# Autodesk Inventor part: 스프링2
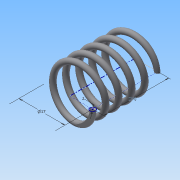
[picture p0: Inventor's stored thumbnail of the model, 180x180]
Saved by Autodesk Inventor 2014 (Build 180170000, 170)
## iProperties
Created: 2016-01
Part Number: 스프링2
Material: 강철, 탄소
Document SubType Name: Modeling
Designer: Administrator
Density: 7.87 g/cm^3
Appearance: 반연마
Mass: 6.44239 g
Surface Area: 16.6857 cm^2
Volume: 0.818602 cm^3
Author: Administrator
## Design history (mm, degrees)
sketch "스케치1"
  geometry: L1 (0, 0)-(8.5, 0); L2 (8.5, 0)-(8.5, 17.5); L3 (8.5, 17.5)-(0, 17.5); L4 (0, 17.5)-(0, 0); C1 r 1 at (8.5, 0)
  constraints: 8 end point, 2 parallel, 1 centre point, 1 coincident, 1 horizontal, 1 perpendicular
  dimensions: "d0" = 17 diameter of L2 L4; "d1" = 17.5 distance of L1.end L2.end (derived); "d2" = 2 diameter of C1
feature "코일1" sketch "스케치1" pitch "d3" = 10; turns "d5" = 5; dims "d4" = 17.5 (= d1), "d6" = 0, angle "d7" = 90 deg, angle "d8" = 90 deg, "d9" = 0, "d10" = 0
node "작업 평면2"
  node "작업 평면1"
sketch "스케치2"
  geometry: L1 (-9.5, 0)-(-7.5, 0) reference; 1 further point
  constraints: 1 horizontal alignment
extrude "돌출1" cut sketch "스케치2" stored distance "d13" = 10; taper "d14" = 0 deg
sketch "스케치3"
  geometry: L1 (-7.5, 0)-(-9.5, 0) reference; 1 further point
  constraints: 1 horizontal alignment
extrude "돌출2" cut sketch "스케치3" stored distance "d15" = 10; taper "d16" = 0 deg
node "솔리드1"
node "절단 모서리 투영1"
node "절단 모서리 투영2"
other parameters: "d11" = 0, "d12" = 17.5 (= d1)
